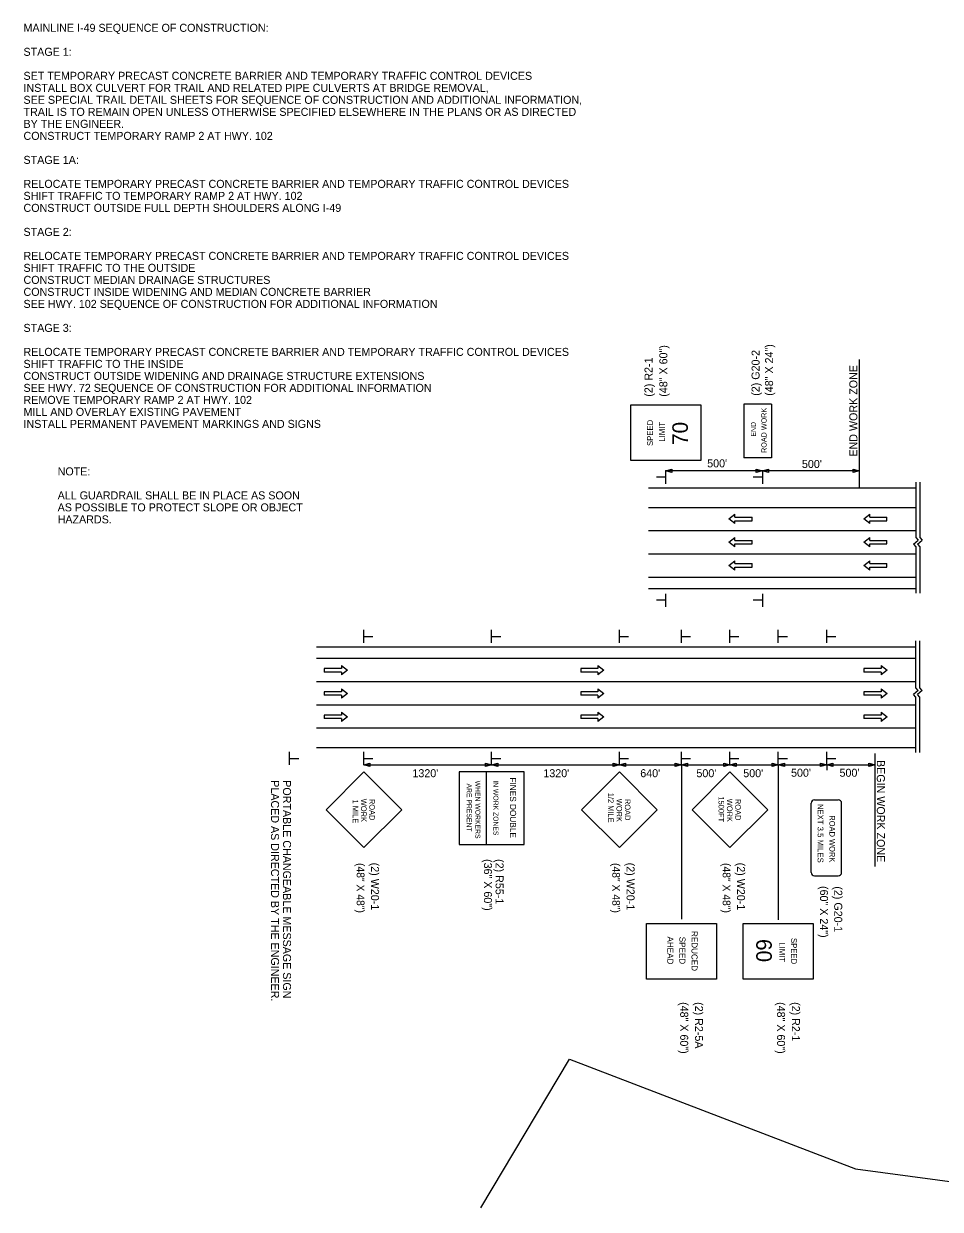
# Model space of a CAD drawing. Extents: x 1017892 to 1236694, y 658553 to 792468.
# Drawn here: x 1021326 to 1023101, y 658553 to 660850 of the extents above; entities that cross this region are included whole.
import ezdxf

# ---------------------------------------------------------------- set-up
doc = ezdxf.new("R2010")
doc.units = 0
for name, color, linetype in [('Level 1', 7, 'Continuous'), ('Level 3', 7, 'Continuous'), ('Level 42', 7, 'Continuous'), ('Level 8', 7, 'Continuous'), ('R_Border', 7, 'Continuous'), ('R_Const Phase All', 7, 'Continuous'), ('R_Proposed Road Annot', 7, 'Continuous')]:
    doc.layers.add(name, color=color, linetype=linetype)

msp = doc.modelspace()

# ---------------------------------------------------------------- linework, layer by layer
at = {"layer": 'Level 1'}
for p, q in [((1022691.6, 659890.1), (1022703.3, 659899.1)), ((1022703.3, 659881.1), (1022691.6, 659890.1)), ((1022703.3, 659893.5), (1022703.3, 659899.1)), ((1022703.3, 659893.5), (1022736.4, 659893.5)), ((1022703.3, 659886.7), (1022736.4, 659886.7)), ((1022703.3, 659881.1), (1022703.3, 659886.7)), ((1022736.4, 659886.7), (1022736.4, 659893.5)), ((1022952.5, 659890.1), (1022964.2, 659899.1)), ((1022964.2, 659881.1), (1022952.5, 659890.1)), ((1022964.2, 659893.5), (1022964.2, 659899.1)), ((1022964.2, 659893.5), (1022997.3, 659893.5)), ((1022964.2, 659886.7), (1022997.3, 659886.7)), ((1022964.2, 659881.1), (1022964.2, 659886.7)), ((1022997.3, 659886.7), (1022997.3, 659893.5)), ((1022691.6, 659845.1), (1022703.3, 659854.1)), ((1022703.3, 659836.1), (1022691.6, 659845.1)), ((1022703.3, 659848.5), (1022703.3, 659854.1)), ((1022703.3, 659848.5), (1022736.4, 659848.5)), ((1022703.3, 659841.7), (1022736.4, 659841.7)), ((1022703.3, 659836.1), (1022703.3, 659841.7)), ((1022736.4, 659841.7), (1022736.4, 659848.5)), ((1022952.5, 659845.1), (1022964.2, 659854.1)), ((1022964.2, 659836.1), (1022952.5, 659845.1)), ((1022964.2, 659848.5), (1022964.2, 659854.1)), ((1022964.2, 659848.5), (1022997.3, 659848.5)), ((1022964.2, 659841.7), (1022997.3, 659841.7)), ((1022964.2, 659836.1), (1022964.2, 659841.7)), ((1022997.3, 659841.7), (1022997.3, 659848.5)), ((1022691.6, 659800.1), (1022703.3, 659809.1)), ((1022703.3, 659791.1), (1022691.6, 659800.1)), ((1022703.3, 659803.5), (1022703.3, 659809.1)), ((1022703.3, 659803.5), (1022736.4, 659803.5)), ((1022703.3, 659796.7), (1022736.4, 659796.7)), ((1022703.3, 659791.1), (1022703.3, 659796.7)), ((1022736.4, 659796.7), (1022736.4, 659803.5)), ((1022952.5, 659800.1), (1022964.2, 659809.1)), ((1022964.2, 659791.1), (1022952.5, 659800.1)), ((1022964.2, 659803.5), (1022964.2, 659809.1)), ((1022964.2, 659803.5), (1022997.3, 659803.5)), ((1022964.2, 659796.7), (1022997.3, 659796.7)), ((1022964.2, 659791.1), (1022964.2, 659796.7)), ((1022997.3, 659796.7), (1022997.3, 659803.5)), ((1021941.4, 659600.3), (1021908.3, 659600.3)), ((1021908.3, 659600.3), (1021908.3, 659593.6)), ((1021941.4, 659593.6), (1021908.3, 659593.6)), ((1021941.4, 659606), (1021941.4, 659600.3)), ((1021941.4, 659606), (1021953, 659597)), ((1021953, 659597), (1021941.4, 659588)), ((1021941.4, 659593.6), (1021941.4, 659588)), ((1022437.9, 659600.3), (1022404.8, 659600.3)), ((1022404.8, 659600.3), (1022404.8, 659593.6)), ((1022437.9, 659593.6), (1022404.8, 659593.6)), ((1022437.9, 659606), (1022437.9, 659600.3)), ((1022437.9, 659606), (1022449.6, 659597)), ((1022449.6, 659597), (1022437.9, 659588)), ((1022437.9, 659593.6), (1022437.9, 659588)), ((1022986.2, 659600.3), (1022953.1, 659600.3)), ((1022953.1, 659600.3), (1022953.1, 659593.6)), ((1022986.2, 659593.6), (1022953.1, 659593.6)), ((1022986.2, 659606), (1022986.2, 659600.3)), ((1022986.2, 659606), (1022997.9, 659597)), ((1022997.9, 659597), (1022986.2, 659588)), ((1022986.2, 659593.6), (1022986.2, 659588)), ((1021941.4, 659561), (1021941.4, 659555.3)), ((1021941.4, 659561), (1021953, 659552)), ((1022437.9, 659561), (1022437.9, 659555.3)), ((1022437.9, 659561), (1022449.6, 659552)), ((1022986.2, 659561), (1022986.2, 659555.3)), ((1022986.2, 659561), (1022997.9, 659552)), ((1021941.4, 659555.3), (1021908.3, 659555.3)), ((1021908.3, 659555.3), (1021908.3, 659548.6)), ((1021941.4, 659548.6), (1021908.3, 659548.6)), ((1021953, 659552), (1021941.4, 659543)), ((1021941.4, 659548.6), (1021941.4, 659543)), ((1022437.9, 659555.3), (1022404.8, 659555.3)), ((1022404.8, 659555.3), (1022404.8, 659548.6)), ((1022437.9, 659548.6), (1022404.8, 659548.6)), ((1022449.6, 659552), (1022437.9, 659543)), ((1022437.9, 659548.6), (1022437.9, 659543)), ((1022986.2, 659555.3), (1022953.1, 659555.3)), ((1022953.1, 659555.3), (1022953.1, 659548.6)), ((1022986.2, 659548.6), (1022953.1, 659548.6)), ((1022997.9, 659552), (1022986.2, 659543)), ((1022986.2, 659548.6), (1022986.2, 659543)), ((1021941.4, 659516), (1021941.4, 659510.3)), ((1021941.4, 659516), (1021953, 659507)), ((1022437.9, 659516), (1022437.9, 659510.3)), ((1022437.9, 659516), (1022449.6, 659507)), ((1022986.2, 659516), (1022986.2, 659510.3)), ((1022986.2, 659516), (1022997.9, 659507)), ((1021941.4, 659510.3), (1021908.3, 659510.3)), ((1021908.3, 659510.3), (1021908.3, 659503.6)), ((1021941.4, 659503.6), (1021908.3, 659503.6)), ((1021953, 659507), (1021941.4, 659498)), ((1021941.4, 659503.6), (1021941.4, 659498)), ((1022437.9, 659510.3), (1022404.8, 659510.3)), ((1022404.8, 659510.3), (1022404.8, 659503.6)), ((1022437.9, 659503.6), (1022404.8, 659503.6)), ((1022449.6, 659507), (1022437.9, 659498)), ((1022437.9, 659503.6), (1022437.9, 659498)), ((1022986.2, 659510.3), (1022953.1, 659510.3)), ((1022953.1, 659510.3), (1022953.1, 659503.6)), ((1022986.2, 659503.6), (1022953.1, 659503.6)), ((1022997.9, 659507), (1022986.2, 659498)), ((1022986.2, 659503.6), (1022986.2, 659498)), ((1022222.2, 659259.3), (1022222.2, 659400))]:
    msp.add_line(p, q, dxfattribs=at)
at = {"layer": 'Level 3'}
for p, q in [((1022569, 659983.4), (1022569, 659958.1)), ((1022756.5, 659983.4), (1022756.5, 659958.1)), ((1022568.6, 659970.8), (1022551.3, 659970.8)), ((1022756.1, 659970.8), (1022738.8, 659970.8)), ((1022569, 659745.1), (1022569, 659719.8)), ((1022756.5, 659745.1), (1022756.5, 659719.8)), ((1022568.6, 659732.5), (1022551.3, 659732.5)), ((1022756.1, 659732.5), (1022738.8, 659732.5)), ((1021984.7, 659650), (1021984.7, 659675.3)), ((1022232.2, 659650), (1022232.2, 659675.3)), ((1022479.7, 659650), (1022479.7, 659675.3)), ((1022599.7, 659650), (1022599.7, 659675.3)), ((1022693.5, 659650), (1022693.5, 659675.3)), ((1022787.2, 659650), (1022787.2, 659675.3)), ((1022881, 659650), (1022881, 659675.3)), ((1021985.1, 659662.6), (1022002.4, 659662.6)), ((1022232.6, 659662.6), (1022249.9, 659662.6)), ((1022480.1, 659662.6), (1022497.4, 659662.6)), ((1022600.1, 659662.6), (1022617.4, 659662.6)), ((1022693.9, 659662.6), (1022711.1, 659662.6)), ((1022787.6, 659662.6), (1022804.9, 659662.6)), ((1022881.4, 659662.6), (1022898.6, 659662.6)), ((1021841, 659413.7), (1021841, 659439)), ((1021841.4, 659426.2), (1021858.7, 659426.2)), ((1021984.7, 659413.7), (1021984.7, 659439)), ((1021985.1, 659426.2), (1022002.4, 659426.2)), ((1022232.2, 659413.7), (1022232.2, 659439)), ((1022232.6, 659426.2), (1022249.9, 659426.2)), ((1022479.7, 659413.7), (1022479.7, 659439)), ((1022480.1, 659426.2), (1022497.4, 659426.2)), ((1022599.7, 659413.7), (1022599.7, 659439)), ((1022600.1, 659426.2), (1022617.4, 659426.2)), ((1022693.5, 659413.7), (1022693.5, 659439)), ((1022693.9, 659426.2), (1022711.1, 659426.2)), ((1022787.2, 659413.7), (1022787.2, 659439)), ((1022787.6, 659426.2), (1022804.9, 659426.2)), ((1022881, 659413.7), (1022881, 659439)), ((1022881.4, 659426.2), (1022898.6, 659426.2))]:
    msp.add_line(p, q, dxfattribs=at)
msp.add_lwpolyline([(1022295.1, 659400), (1022169.4, 659400), (1022169.4, 659259.3), (1022295.1, 659259.3)], close=True, dxfattribs=at)
for centre, start, end in [((1022857.2, 659339.3), 90, 180), ((1022903.3, 659339.3), 0, 90), ((1022857.2, 659205.3), 180, 270), ((1022903.3, 659205.3), 270, 0)]:
    msp.add_arc(centre, 6.46, start, end, dxfattribs=at)
at = {"layer": 'Level 42'}
for p, q in [((1022850.7, 659205.3), (1022850.7, 659339.3)), ((1022857.2, 659345.7), (1022903.3, 659345.7)), ((1022909.7, 659205.3), (1022909.7, 659339.3)), ((1022857.2, 659198.9), (1022903.3, 659198.9))]:
    msp.add_line(p, q, dxfattribs=at)
at = {"layer": 'Level 8'}
for p, q in [((1022720.2, 660112.3), (1022720.2, 660008.7)), ((1022773.9, 660112.3), (1022720.2, 660112.3)), ((1022773.9, 660112.3), (1022773.9, 660008.7)), ((1022773.9, 660008.7), (1022720.2, 660008.7)), ((1021911.8, 659326.7), (1021985.1, 659400)), ((1022058.4, 659326.7), (1021985.1, 659400)), ((1022406.5, 659326.7), (1022479.7, 659400)), ((1022553, 659326.7), (1022479.7, 659400)), ((1022620.2, 659326.7), (1022693.5, 659400)), ((1022766.8, 659326.7), (1022693.5, 659400)), ((1021985.1, 659253.4), (1021911.8, 659326.7)), ((1021985.1, 659253.4), (1022058.4, 659326.7)), ((1022479.7, 659253.4), (1022406.5, 659326.7)), ((1022479.7, 659253.4), (1022553, 659326.7)), ((1022693.5, 659253.4), (1022620.2, 659326.7)), ((1022693.5, 659253.4), (1022766.8, 659326.7))]:
    msp.add_line(p, q, dxfattribs=at)
for points in [[(1022501.6, 660111), (1022637, 660111), (1022637, 660003.5), (1022501.6, 660003.5)], [(1022667.5, 658998.8), (1022532, 658998.8), (1022532, 659106.3), (1022667.5, 659106.3)], [(1022855, 658998.8), (1022719.5, 658998.8), (1022719.5, 659106.3), (1022855, 659106.3)]]:
    msp.add_lwpolyline(points, close=True, dxfattribs=at)
at = {"layer": 'R_Border'}
for points in [[(1022936.9, 658631.4), (1023518.7, 658552.8), (1024274.9, 658880.1)], [(1022211.2, 658555.5), (1022383, 658843.5), (1022936.9, 658631.4)]]:
    msp.add_lwpolyline(points, dxfattribs=at)
at = {"layer": 'R_Const Phase All'}
for p, q in [((1023053.4, 659961.2), (1023053.4, 659854.3)), ((1023060.9, 659961.2), (1023060.9, 659854.3)), ((1022535.9, 659950.1), (1023053.4, 659950.1)), ((1022535.9, 659912.6), (1023053.4, 659912.6)), ((1022535.9, 659867.6), (1023053.4, 659867.6)), ((1023049, 659841.4), (1023057.9, 659849.1)), ((1023049, 659841.4), (1023053.5, 659836.2)), ((1023053.4, 659854.3), (1023057.9, 659849.1)), ((1023053.5, 659836.2), (1023053.4, 659746.5)), ((1023056.5, 659841.4), (1023065.4, 659849.1)), ((1023056.5, 659841.4), (1023061, 659836.2)), ((1023060.9, 659854.3), (1023065.4, 659849.1)), ((1023061, 659836.2), (1023060.9, 659746.5)), ((1022535.9, 659822.6), (1023053.4, 659822.6)), ((1022535.9, 659777.6), (1023053.4, 659777.6)), ((1022535.9, 659755.1), (1023053.4, 659755.1)), ((1023053.4, 659562.8), (1023053.4, 659653.8)), ((1023060.9, 659562.8), (1023060.9, 659653.8)), ((1023053.4, 659642), (1021893, 659642)), ((1023053.4, 659619.5), (1021893, 659619.5)), ((1023053.4, 659574.5), (1021893, 659574.5)), ((1023057.9, 659557.6), (1023053.4, 659562.8)), ((1023065.4, 659557.6), (1023060.9, 659562.8)), ((1023057.9, 659557.6), (1023048.9, 659549.8)), ((1023053.4, 659544.6), (1023048.9, 659549.8)), ((1023053.4, 659437.8), (1023053.4, 659544.6)), ((1023065.4, 659557.6), (1023056.4, 659549.8)), ((1023060.9, 659544.6), (1023056.4, 659549.8)), ((1023060.9, 659437.8), (1023060.9, 659544.6)), ((1023053.4, 659529.5), (1021893, 659529.5)), ((1023053.4, 659484.5), (1021893, 659484.5)), ((1023053.4, 659447), (1021893, 659447))]:
    msp.add_line(p, q, dxfattribs=at)
at = {"layer": 'R_Proposed Road Annot'}
for p, q in [((1022944, 660198.8), (1022944, 659949.6)), ((1022974.7, 659217.1), (1022974.7, 659435.7)), ((1022599.7, 659413.7), (1022599.7, 659115.1)), ((1022787.2, 659413.7), (1022787.2, 659113.3)), ((1022881, 659413.7), (1022881, 659403.7))]:
    msp.add_line(p, q, dxfattribs=at)
for points in [[(1022581, 659980.4), (1022569, 659983.4), (1022581, 659986.4)], [(1022744.5, 659986.4), (1022756.5, 659983.4), (1022744.5, 659980.4)], [(1022768.5, 659980.4), (1022756.5, 659983.4), (1022768.5, 659986.4)], [(1022932, 659986.4), (1022944, 659983.4), (1022932, 659980.4)], [(1021996.7, 659410.7), (1021984.7, 659413.7), (1021996.7, 659416.7)], [(1022220.2, 659416.7), (1022232.2, 659413.7), (1022220.2, 659410.7)], [(1022244.2, 659410.7), (1022232.2, 659413.7), (1022244.2, 659416.7)], [(1022467.7, 659416.7), (1022479.7, 659413.7), (1022467.7, 659410.7)], [(1022491.7, 659410.7), (1022479.7, 659413.7), (1022491.7, 659416.7)], [(1022587.7, 659416.7), (1022599.7, 659413.7), (1022587.7, 659410.7)], [(1022611.7, 659410.7), (1022599.7, 659413.7), (1022611.7, 659416.7)], [(1022681.5, 659416.7), (1022693.5, 659413.7), (1022681.5, 659410.7)], [(1022705.5, 659410.7), (1022693.5, 659413.7), (1022705.5, 659416.7)], [(1022775.2, 659416.7), (1022787.2, 659413.7), (1022775.2, 659410.7)], [(1022799.2, 659410.7), (1022787.2, 659413.7), (1022799.2, 659416.7)], [(1022869, 659416.7), (1022881, 659413.7), (1022869, 659410.7)], [(1022893, 659410.7), (1022881, 659413.7), (1022893, 659416.7)], [(1022962.7, 659416.7), (1022974.7, 659413.7), (1022962.7, 659410.7)]]:
    msp.add_lwpolyline(points, close=True, dxfattribs=at)
for points in [[(1022756.5, 659983.4), (1022569, 659983.4)], [(1022944, 659983.4), (1022756.5, 659983.4)], [(1021984.7, 659413.7), (1022232.2, 659413.7)], [(1022232.2, 659413.7), (1022479.7, 659413.7)], [(1022479.7, 659413.7), (1022599.7, 659413.7)], [(1022599.7, 659413.7), (1022693.5, 659413.7)], [(1022693.5, 659413.7), (1022787.2, 659413.7)], [(1022787.2, 659413.7), (1022881, 659413.7)], [(1022881, 659413.7), (1022974.7, 659413.7)]]:
    msp.add_lwpolyline(points, dxfattribs=at)

# ---------------------------------------------------------------- texts
at = {"layer": 'Level 3'}
for s, height, rotation, p in [('ROAD WORK', 10.07, 90, (1022764.5, 660018.1)), ('NEXT 3.5 MILES', 11.194, 270, (1022863.3, 659338.1))]:
    msp.add_text(s, height=height, rotation=rotation, dxfattribs=at).set_placement(p)
at = {"layer": 'Level 42'}
for s, height, rotation, p in [('END', 9.76, 90, (1022743.8, 660049.5)), ('ROAD WORK', 10.85, 270, (1022886.2, 659316))]:
    msp.add_text(s, height=height, rotation=rotation, dxfattribs=at).set_placement(p)
at = {"layer": 'Level 8'}
for s, height, rotation, p in [('(48" X 24")', 15.5, 90.0004, (1022777.1, 660128.7)), ('(48" X 60")', 15.5, 90, (1022572.4, 660126.9)), ('(2) G20-2', 15.5, 90.0004, (1022751, 660128.7)), ('(2) R2-1', 15.5, 90, (1022543.7, 660126.9)), ('SPEED', 11.19, 90, (1022544.5, 660031.5)), ('LIMIT', 11.19, 90, (1022567.7, 660040)), ('70', 30, 90, (1022612.1, 660033.5)), ('ARE PRESENT', 9.552, 270, (1022184.1, 659377.6)), ('WHEN WORKERS', 9.552, 270, (1022200.8, 659383.1)), ('IN WORK ZONES', 9.55, 270, (1022235.8, 659383.9)), ('FINES DOUBLE', 11.94, 270, (1022267.7, 659389.3)), ('1/2 MILE', 10.8, 270.0006, (1022457.8, 659359.6)), ('1 MILE', 10.8, 270.0006, (1021963.1, 659346.4)), ('WORK', 10.8, 270, (1021979.3, 659348)), ('ROAD', 10.8, 270.0004, (1021995.5, 659347.8)), ('WORK', 10.8, 270, (1022474, 659348)), ('ROAD', 10.8, 270.0004, (1022490.2, 659347.8)), ('1500FT', 10.8, 270.0006, (1022671.5, 659352.6)), ('WORK', 10.8, 270, (1022687.7, 659348)), ('ROAD', 10.8, 270.0004, (1022703.9, 659347.8)), ('(48" X 48")', 15, 270, (1021971.1, 659223.6)), ('(2) W20-1', 15.5, 270, (1021998.8, 659224.2)), ('(36" X 60")', 15.5, 270, (1022217.4, 659231.2)), ('(2) R55-1', 15.5, 270, (1022239.9, 659231.2)), ('(48" X 48")', 15, 270, (1022465.8, 659223.6)), ('(2) W20-1', 15.5, 270, (1022493.5, 659224.2)), ('(48" X 48")', 15, 270, (1022679.6, 659223.6)), ('(2) W20-1', 15.5, 270, (1022707.3, 659224.2)), ('(60" X 24")', 15.5, 270, (1022868, 659179)), ('(2) G20-1', 15.5, 270, (1022895.5, 659178.4)), ('AHEAD', 11.72, 270, (1022572.4, 659081.2)), ('SPEED', 11.72, 270, (1022595.8, 659080.7)), ('REDUCED', 11.72, 270, (1022619.2, 659091.8)), ('60', 30, 270, (1022744.5, 659076.3)), ('LIMIT', 11.19, 270, (1022788.9, 659069.8)), ('SPEED', 11.19, 270, (1022812, 659078.3)), ('(48" X 60")', 15.5, 270, (1022597.3, 658954.1)), ('(2) R2-5A', 15.5, 270, (1022626, 658954.1)), ('(48" X 60")', 15.5, 270, (1022784.8, 658954.1)), ('(2) R2-1', 15.5, 270, (1022813.5, 658954.1))]:
    msp.add_text(s, height=height, rotation=rotation, dxfattribs=at).set_placement(p)
at = {"layer": 'R_Const Phase All'}
for s, p in [('PLACED AS DIRECTED BY THE ENGINEER.', (1021805.2, 659383.9)), ('PORTABLE CHANGEABLE MESSAGE SIGN ', (1021828.4, 659383.9))]:
    msp.add_text(s, height=15.5, rotation=270, dxfattribs=at).set_placement(p)
at = {"layer": 'R_Proposed Road Annot'}
for s, p in [('MAINLINE I-49 SEQUENCE OF CONSTRUCTION:', (1021326, 660833.8)), ('STAGE 1:', (1021326, 660787.3)), ('SET TEMPORARY PRECAST CONCRETE BARRIER AND TEMPORARY TRAFFIC CONTROL DEVICES', (1021326, 660740.8)), ('INSTALL BOX CULVERT FOR TRAIL AND RELATED PIPE CULVERTS AT BRIDGE REMOVAL,', (1021326, 660717.5)), ('SEE SPECIAL TRAIL DETAIL SHEETS FOR SEQUENCE OF CONSTRUCTION AND ADDITIONAL INFORMATION, ', (1021326, 660694.3)), ('TRAIL IS TO REMAIN OPEN UNLESS OTHERWISE SPECIFIED ELSEWHERE IN THE PLANS OR AS DIRECTED', (1021326, 660671)), ('BY THE ENGINEER.', (1021326, 660647.8)), ('CONSTRUCT TEMPORARY RAMP 2 AT HWY. 102', (1021326, 660624.5)), ('STAGE 1A:', (1021326, 660578)), ('RELOCATE TEMPORARY PRECAST CONCRETE BARRIER AND TEMPORARY TRAFFIC CONTROL DEVICES', (1021326, 660531.5)), ('SHIFT TRAFFIC TO TEMPORARY RAMP 2 AT HWY. 102', (1021326, 660508.3)), ('CONSTRUCT OUTSIDE FULL DEPTH SHOULDERS ALONG I-49', (1021326, 660485)), ('STAGE 2:', (1021326, 660438.5)), ('RELOCATE TEMPORARY PRECAST CONCRETE BARRIER AND TEMPORARY TRAFFIC CONTROL DEVICES', (1021326, 660392)), ('SHIFT TRAFFIC TO THE OUTSIDE', (1021326, 660368.8)), ('CONSTRUCT MEDIAN DRAINAGE STRUCTURES', (1021326, 660345.5)), ('CONSTRUCT INSIDE WIDENING AND MEDIAN CONCRETE BARRIER', (1021326, 660322.3)), ('SEE HWY. 102 SEQUENCE OF CONSTRUCTION FOR ADDITIONAL INFORMATION', (1021326, 660299)), ('STAGE 3:', (1021326, 660252.5)), ('RELOCATE TEMPORARY PRECAST CONCRETE BARRIER AND TEMPORARY TRAFFIC CONTROL DEVICES', (1021326, 660206)), ('SHIFT TRAFFIC TO THE INSIDE ', (1021326, 660182.8)), ('CONSTRUCT OUTSIDE WIDENING AND DRAINAGE STRUCTURE EXTENSIONS', (1021326, 660159.5)), ('SEE HWY. 72 SEQUENCE OF CONSTRUCTION FOR ADDITIONAL INFORMATION', (1021326, 660136.3)), ('REMOVE TEMPORARY RAMP 2 AT HWY. 102', (1021326, 660113)), ('MILL AND OVERLAY EXISTING PAVEMENT', (1021326, 660089.8)), ('INSTALL PERMANENT PAVEMENT MARKINGS AND SIGNS', (1021326, 660066.5)), ("500'", (1022649.5, 659990.1)), ("500'", (1022833, 659988.9)), ('NOTE:', (1021392.1, 659974.5)), ('ALL GUARDRAIL SHALL BE IN PLACE AS SOON ', (1021392.1, 659928)), ('AS POSSIBLE TO PROTECT SLOPE OR OBJECT ', (1021392.1, 659904.8)), ('HAZARDS.', (1021392.1, 659881.5)), ("1320'", (1022078.9, 659389.8)), ("1320'", (1022332.4, 659389.8)), ("640'", (1022520, 659389.8)), ("500'", (1022628.7, 659389.8)), ("500'", (1022719.4, 659389.8)), ("500'", (1022811.9, 659390.7)), ("500'", (1022905.7, 659390.7))]:
    msp.add_text(s, height=15.5, dxfattribs=at).set_placement(p)
for s, rotation, p in [('END WORK ZONE', 90, (1022940.3, 660010.9)), ('BEGIN WORK ZONE', 270, (1022978, 659423.1))]:
    msp.add_text(s, height=15.5, rotation=rotation, dxfattribs=at).set_placement(p)

doc.saveas('drawing.dxf')
